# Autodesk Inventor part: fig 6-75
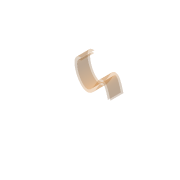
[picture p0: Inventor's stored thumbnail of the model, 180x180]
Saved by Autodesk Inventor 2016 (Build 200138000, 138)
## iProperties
Shininess: 64.0
Length Units: 11269
Angle Units: 11279
Time Units: 11290
Mass Units: 11283
Length Display Precision: 3
Angle Display Precision: 2
Compacted: True
Part Number: fig 6-75
Document SubType Name: Modeling
Created: 2002-12
Designer: deepak
Density: 1 g/cm^3
Material: Generic
Appearance: Default
Density: 0.0
Volumn: 0.0
Area: 0.0
PropertySet Name: Model Information
Control State: 0
Master: False
Checked Out: False
Author: deepak
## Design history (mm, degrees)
sketch "Sketch1"
  geometry: 5 further points
  constraints: 5 other
extrude_surface "ExtrusionSrf1" sketch "Sketch1" dims "d0" = 20, "d1" = 0
feature "OffsetSrf2" dims "d8" = 4, "d9" = 4
body "Solid1"
body "Srf1"
body "Srf2"
